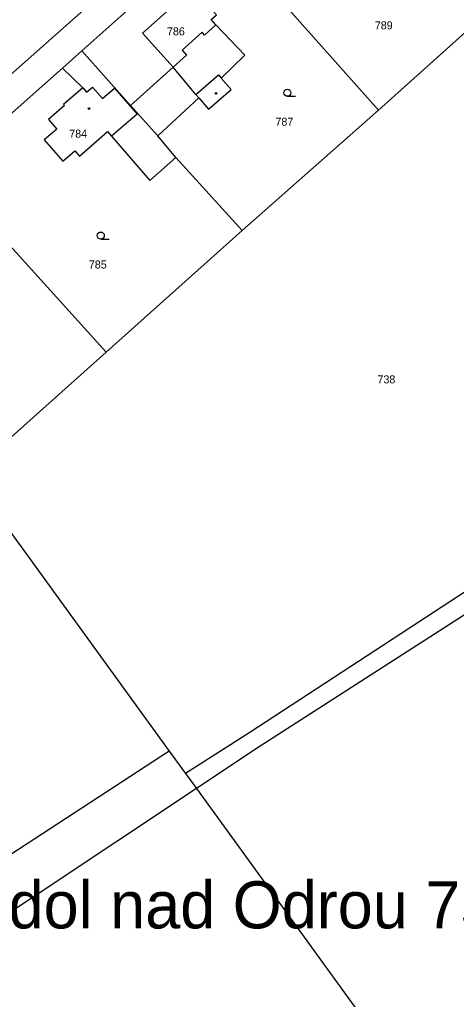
# Model space of a CAD drawing. Extents: x -504988 to -494607, y -1123820 to -1114018.
# Drawn here: x -497381.1 to -497288.4, y -1120642 to -1120433.9 of the extents above; entities that cross this region are included whole.
import ezdxf

# ---------------------------------------------------------------- set-up
doc = ezdxf.new("R2010")
doc.units = 0
for name, color, linetype in [('Hranice parcel', 7, 'Continuous'), ('Parcelní čísla', 7, 'Continuous'), ('Pop  PČ popisy', 7, 'Continuous'), ('Vnitřní kresba', 7, 'Continuous'), ('Značky budov', 7, 'Continuous'), ('Značky kultur', 7, 'Continuous')]:
    doc.layers.add(name, color=color, linetype=linetype)

msp = doc.modelspace()

# ---------------------------------------------------------------- linework, layer by layer
at = {"layer": 'Hranice parcel'}
for p, q in [((-497367.93, -1120440.59), (-497339.11, -1120414.82)), ((-497304.91, -1120453.15), (-497339.11, -1120414.82)), ((-497383.69, -1120446.26), (-497365.62, -1120430.15)), ((-497285.67, -1120435.92), (-497304.91, -1120453.15)), ((-497372.05, -1120444.24), (-497367.93, -1120440.59)), ((-497357.61, -1120452.15), (-497367.93, -1120440.59)), ((-497397.19, -1120466.49), (-497372.05, -1120444.24)), ((-497351.81, -1120458.64), (-497357.61, -1120452.15)), ((-497304.91, -1120453.15), (-497333.88, -1120478.71)), ((-497347.96, -1120463.21), (-497351.81, -1120458.64)), ((-497333.88, -1120478.71), (-497347.96, -1120463.21)), ((-497362.78, -1120504.56), (-497397.19, -1120466.49)), ((-497333.88, -1120478.71), (-497362.78, -1120504.56)), ((-497362.78, -1120504.56), (-497385.68, -1120524.98)), ((-497391.95, -1120530.57), (-497349.37, -1120589.26)), ((-497349.37, -1120589.26), (-497345.91, -1120594.04)), ((-497345.91, -1120594.04), (-497343.59, -1120597.23)), ((-497343.59, -1120597.23), (-497244.66, -1120733.63))]:
    msp.add_line(p, q, dxfattribs=at)
for points in [[(-497351.81, -1120458.64), (-497343.11, -1120450.57), (-497341.04, -1120452.95), (-497336.24, -1120448.76), (-497338.32, -1120446.37), (-497333.33, -1120441.48), (-497339.46, -1120435.06), (-497340.45, -1120433.95), (-497339.33, -1120432.94), (-497342.47, -1120429.47), (-497343.59, -1120430.48), (-497345.56, -1120428.3), (-497355.02, -1120436.84), (-497348.53, -1120444.03), (-497357.61, -1120452.15)], [(-497372.05, -1120444.24), (-497367.72, -1120448.45), (-497371.8, -1120451.98), (-497371.6, -1120452.21), (-497374.99, -1120455.15), (-497373.23, -1120457.18), (-497375.9, -1120459.5), (-497371.98, -1120464.03), (-497369.42, -1120461.81), (-497368.45, -1120462.92), (-497362.46, -1120457.73), (-497361.63, -1120458.7), (-497353.47, -1120468.09), (-497347.96, -1120463.21)], [(-497228.87, -1120517.83), (-497262.8, -1120539.95), (-497332.28, -1120585.34), (-497345.91, -1120594.04)], [(-497240.19, -1120530.3), (-497260.54, -1120543.54), (-497330.29, -1120588.38), (-497343.59, -1120597.23)], [(-497349.37, -1120589.26), (-497477.01, -1120672.48), (-497604.63, -1120755.71), (-497698.4, -1120816.44), (-497821.04, -1120898.04), (-497931.33, -1120969.32), (-498041.62, -1121040.59), (-498124.46, -1121095.39), (-498243.47, -1121172.51), (-498264.79, -1121187.65), (-498296.3, -1121208.05), (-498309.12, -1121214.61), (-498319.07, -1121213.07), (-498324.96, -1121206.38)], [(-497343.59, -1120597.23), (-497446.2, -1120665.45), (-497531.34, -1120721.63), (-497616.47, -1120777.81), (-497720.15, -1120845.42), (-497823.83, -1120913.02), (-497984.58, -1121017.48), (-498052.05, -1121061.59), (-498108.05, -1121098.26)]]:
    msp.add_lwpolyline(points, dxfattribs=at)
at = {"layer": 'Vnitřní kresba'}
for p, q in [((-497339.46, -1120435.06), (-497341.86, -1120437.23)), ((-497342.4, -1120436.64), (-497346.62, -1120440.45)), ((-497341.86, -1120437.23), (-497342.4, -1120436.64)), ((-497345.7, -1120441.48), (-497348.53, -1120444.03)), ((-497346.62, -1120440.45), (-497345.7, -1120441.48)), ((-497343.74, -1120449.84), (-497348.53, -1120444.03)), ((-497343.74, -1120449.84), (-497338.94, -1120445.66)), ((-497338.94, -1120445.66), (-497338.32, -1120446.37)), ((-497367.72, -1120448.45), (-497366.92, -1120449.37)), ((-497366.92, -1120449.37), (-497365.66, -1120448.27)), ((-497365.66, -1120448.27), (-497363.56, -1120450.69)), ((-497363.56, -1120450.69), (-497360.99, -1120448.48)), ((-497360.99, -1120448.48), (-497356.2, -1120454)), ((-497343.11, -1120450.57), (-497343.74, -1120449.84)), ((-497356.2, -1120454), (-497361.63, -1120458.7))]:
    msp.add_line(p, q, dxfattribs=at)
at = {"layer": 'Značky budov'}
for centre in [(-497339.44, -1120449.63), (-497366.41, -1120452.83)]:
    msp.add_circle(centre, 0.175, dxfattribs=at)
at = {"layer": 'Značky kultur'}
for p, q in [((-497324.28, -1120450.23), (-497322.53, -1120450.23)), ((-497363.9, -1120480.54), (-497362.15, -1120480.54))]:
    msp.add_line(p, q, dxfattribs=at)
for centre in [(-497324.28, -1120449.48), (-497363.9, -1120479.79)]:
    msp.add_circle(centre, 0.75, dxfattribs=at)

# ---------------------------------------------------------------- texts
at = {"layer": 'Parcelní čísla'}
for s, p in [('789', (-497305.72, -1120436.02)), ('786', (-497349.85, -1120437.29)), ('787', (-497326.82, -1120456.48)), ('784', (-497370.59, -1120459.01)), ('785', (-497366.43, -1120486.79)), ('738', (-497305.16, -1120511.18))]:
    msp.add_text(s, height=1.7, dxfattribs=at).set_placement(p)
at = {"layer": 'Pop  PČ popisy'}
msp.add_text('Suchdol nad Odrou 759163', height=10, dxfattribs=at).set_placement((-497413.95, -1120626.9))

doc.saveas('drawing.dxf')
